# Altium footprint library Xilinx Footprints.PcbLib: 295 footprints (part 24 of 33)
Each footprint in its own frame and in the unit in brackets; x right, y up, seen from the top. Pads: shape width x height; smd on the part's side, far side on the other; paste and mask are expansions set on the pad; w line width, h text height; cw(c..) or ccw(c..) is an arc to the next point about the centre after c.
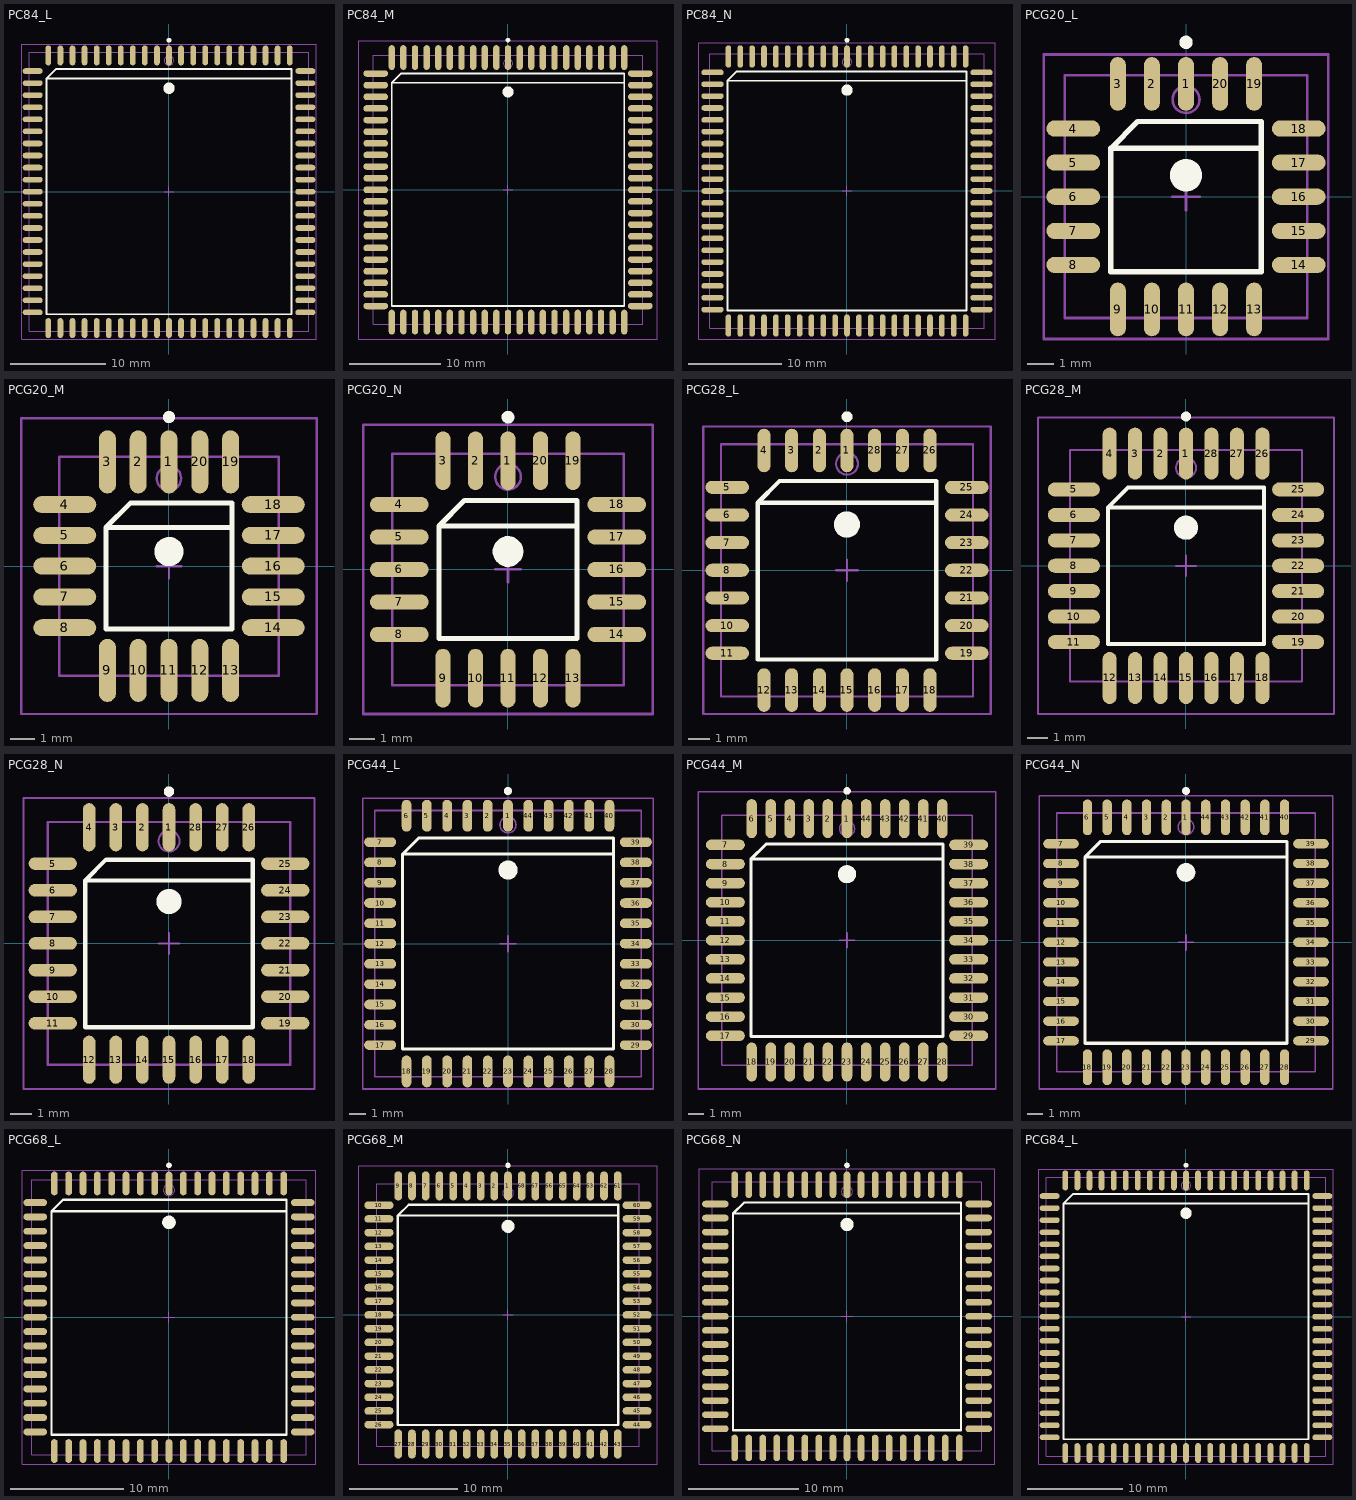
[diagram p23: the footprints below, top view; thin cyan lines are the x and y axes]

## PC84_L [mm] "84-Pin Plastic Leaded Chip Carrier (PC84), IPC High Density"
height 5.08
pads (84):
  oval 0.6x2.1 smd: 1(0,14.35) 2(-1.27,14.35) 3(-2.54,14.35) 4(-3.81,14.35) 5(-5.08,14.35) 6(-6.35,14.35) 7(-7.62,14.35) 8(-8.89,14.35) 9(-10.16,14.35) 10(-11.43,14.35) 11(-12.7,14.35) 33(-12.7,-14.35) 34(-11.43,-14.35) 35(-10.16,-14.35) 36(-8.89,-14.35) 37(-7.62,-14.35) 38(-6.35,-14.35) 39(-5.08,-14.35) 40(-3.81,-14.35) 41(-2.54,-14.35) 42(-1.27,-14.35) 43(0,-14.35) 44(1.27,-14.35) 45(2.54,-14.35) 46(3.81,-14.35) 47(5.08,-14.35) 48(6.35,-14.35) 49(7.62,-14.35) 50(8.89,-14.35) 51(10.16,-14.35) 52(11.43,-14.35) 53(12.7,-14.35) 75(12.7,14.35) 76(11.43,14.35) 77(10.16,14.35) 78(8.89,14.35) 79(7.62,14.35) 80(6.35,14.35) 81(5.08,14.35) 82(3.81,14.35) 83(2.54,14.35) 84(1.27,14.35)
  oval 2.1x0.6 smd: 12(-14.35,12.7) 13(-14.35,11.43) 14(-14.35,10.16) 15(-14.35,8.89) 16(-14.35,7.62) 17(-14.35,6.35) 18(-14.35,5.08) 19(-14.35,3.81) 20(-14.35,2.54) 21(-14.35,1.27) 22(-14.35,0) 23(-14.35,-1.27) 24(-14.35,-2.54) 25(-14.35,-3.81) 26(-14.35,-5.08) 27(-14.35,-6.35) 28(-14.35,-7.62) 29(-14.35,-8.89) 30(-14.35,-10.16) 31(-14.35,-11.43) 32(-14.35,-12.7) 54(14.35,-12.7) 55(14.35,-11.43) 56(14.35,-10.16) 57(14.35,-8.89) 58(14.35,-7.62) 59(14.35,-6.35) 60(14.35,-5.08) 61(14.35,-3.81) 62(14.35,-2.54) 63(14.35,-1.27) 64(14.35,0) 65(14.35,1.27) 66(14.35,2.54) 67(14.35,3.81) 68(14.35,5.08) 69(14.35,6.35) 70(14.35,7.62) 71(14.35,8.89) 72(14.35,10.16) 73(14.35,11.43) 74(14.35,12.7)
Top Overlay:
  circle w0.25: c0,15.95 r0.125
  circle w0.6: c0,10.9 r0.3
  lines w0.2: 12.9,11.9 -12.9,11.9 ; -12.9,11.9 -11.9,12.9 12.9,12.9 12.9,-12.9 -12.9,-12.9 -12.9,11.9
Mechanical 13:
  circle w0.1: c0,13.805 r0.5
  lines w0.1: -14.705,-14.705 -14.705,14.705 14.705,14.705 14.705,-14.705 -14.705,-14.705
Mechanical 15:
  lines w0.1: -0.5,0 0.5,0 ; 0,-0.5 0,0.5 ; -15.5,-15.5 -15.5,15.5 15.5,15.5 15.5,-15.5 -15.5,-15.5
3D body: height 5.08, standoff 0, extent -14.705,-14.705 14.705,14.705

## PC84_M [mm] "84-Pin Plastic Leaded Chip Carrier (PC84), IPC Low Density"
height 5.08
pads (84):
  oval 0.7x2.7 smd: 1(0,14.45) 2(-1.27,14.45) 3(-2.54,14.45) 4(-3.81,14.45) 5(-5.08,14.45) 6(-6.35,14.45) 7(-7.62,14.45) 8(-8.89,14.45) 9(-10.16,14.45) 10(-11.43,14.45) 11(-12.7,14.45) 33(-12.7,-14.45) 34(-11.43,-14.45) 35(-10.16,-14.45) 36(-8.89,-14.45) 37(-7.62,-14.45) 38(-6.35,-14.45) 39(-5.08,-14.45) 40(-3.81,-14.45) 41(-2.54,-14.45) 42(-1.27,-14.45) 43(0,-14.45) 44(1.27,-14.45) 45(2.54,-14.45) 46(3.81,-14.45) 47(5.08,-14.45) 48(6.35,-14.45) 49(7.62,-14.45) 50(8.89,-14.45) 51(10.16,-14.45) 52(11.43,-14.45) 53(12.7,-14.45) 75(12.7,14.45) 76(11.43,14.45) 77(10.16,14.45) 78(8.89,14.45) 79(7.62,14.45) 80(6.35,14.45) 81(5.08,14.45) 82(3.81,14.45) 83(2.54,14.45) 84(1.27,14.45)
  oval 2.7x0.7 smd: 12(-14.45,12.7) 13(-14.45,11.43) 14(-14.45,10.16) 15(-14.45,8.89) 16(-14.45,7.62) 17(-14.45,6.35) 18(-14.45,5.08) 19(-14.45,3.81) 20(-14.45,2.54) 21(-14.45,1.27) 22(-14.45,0) 23(-14.45,-1.27) 24(-14.45,-2.54) 25(-14.45,-3.81) 26(-14.45,-5.08) 27(-14.45,-6.35) 28(-14.45,-7.62) 29(-14.45,-8.89) 30(-14.45,-10.16) 31(-14.45,-11.43) 32(-14.45,-12.7) 54(14.45,-12.7) 55(14.45,-11.43) 56(14.45,-10.16) 57(14.45,-8.89) 58(14.45,-7.62) 59(14.45,-6.35) 60(14.45,-5.08) 61(14.45,-3.81) 62(14.45,-2.54) 63(14.45,-1.27) 64(14.45,0) 65(14.45,1.27) 66(14.45,2.54) 67(14.45,3.81) 68(14.45,5.08) 69(14.45,6.35) 70(14.45,7.62) 71(14.45,8.89) 72(14.45,10.16) 73(14.45,11.43) 74(14.45,12.7)
Top Overlay:
  circle w0.25: c0,16.35 r0.125
  circle w0.6: c0,10.7 r0.3
  lines w0.2: 12.7,11.7 -12.7,11.7 ; -12.7,11.7 -11.7,12.7 12.7,12.7 12.7,-12.7 -12.7,-12.7 -12.7,11.7
Mechanical 13:
  circle w0.1: c0,13.805 r0.5
  lines w0.1: -14.705,-14.705 -14.705,14.705 14.705,14.705 14.705,-14.705 -14.705,-14.705
Mechanical 15:
  lines w0.1: -0.5,0 0.5,0 ; 0,-0.5 0,0.5 ; -16.3,-16.3 -16.3,16.3 16.3,16.3 16.3,-16.3 -16.3,-16.3
3D body: height 5.08, standoff 0, extent -14.705,-14.705 14.705,14.705

## PC84_N [mm] "84-Pin Plastic Leaded Chip Carrier (PC84), IPC Medium Density"
height 5.08
pads (84):
  oval 0.6x2.4 smd: 1(0,14.4) 2(-1.27,14.4) 3(-2.54,14.4) 4(-3.81,14.4) 5(-5.08,14.4) 6(-6.35,14.4) 7(-7.62,14.4) 8(-8.89,14.4) 9(-10.16,14.4) 10(-11.43,14.4) 11(-12.7,14.4) 33(-12.7,-14.4) 34(-11.43,-14.4) 35(-10.16,-14.4) 36(-8.89,-14.4) 37(-7.62,-14.4) 38(-6.35,-14.4) 39(-5.08,-14.4) 40(-3.81,-14.4) 41(-2.54,-14.4) 42(-1.27,-14.4) 43(0,-14.4) 44(1.27,-14.4) 45(2.54,-14.4) 46(3.81,-14.4) 47(5.08,-14.4) 48(6.35,-14.4) 49(7.62,-14.4) 50(8.89,-14.4) 51(10.16,-14.4) 52(11.43,-14.4) 53(12.7,-14.4) 75(12.7,14.4) 76(11.43,14.4) 77(10.16,14.4) 78(8.89,14.4) 79(7.62,14.4) 80(6.35,14.4) 81(5.08,14.4) 82(3.81,14.4) 83(2.54,14.4) 84(1.27,14.4)
  oval 2.4x0.6 smd: 12(-14.4,12.7) 13(-14.4,11.43) 14(-14.4,10.16) 15(-14.4,8.89) 16(-14.4,7.62) 17(-14.4,6.35) 18(-14.4,5.08) 19(-14.4,3.81) 20(-14.4,2.54) 21(-14.4,1.27) 22(-14.4,0) 23(-14.4,-1.27) 24(-14.4,-2.54) 25(-14.4,-3.81) 26(-14.4,-5.08) 27(-14.4,-6.35) 28(-14.4,-7.62) 29(-14.4,-8.89) 30(-14.4,-10.16) 31(-14.4,-11.43) 32(-14.4,-12.7) 54(14.4,-12.7) 55(14.4,-11.43) 56(14.4,-10.16) 57(14.4,-8.89) 58(14.4,-7.62) 59(14.4,-6.35) 60(14.4,-5.08) 61(14.4,-3.81) 62(14.4,-2.54) 63(14.4,-1.27) 64(14.4,0) 65(14.4,1.27) 66(14.4,2.54) 67(14.4,3.81) 68(14.4,5.08) 69(14.4,6.35) 70(14.4,7.62) 71(14.4,8.89) 72(14.4,10.16) 73(14.4,11.43) 74(14.4,12.7)
Top Overlay:
  circle w0.6: c0,10.8 r0.3
  circle w0.25: c0,16.15 r0.125
  lines w0.2: 12.8,11.8 -12.8,11.8 ; -12.8,11.8 -12.8,-12.8 12.8,-12.8 12.8,12.8 -11.8,12.8 -12.8,11.8
Mechanical 13:
  circle w0.1: c0,13.805 r0.5
  lines w0.1: -14.705,-14.705 14.705,-14.705 14.705,14.705 -14.705,14.705 -14.705,-14.705
Mechanical 15:
  lines w0.1: -0.5,0 0.5,0 ; 0,-0.5 0,0.5 ; -15.85,-15.85 15.85,-15.85 15.85,15.85 -15.85,15.85 -15.85,-15.85
3D body: height 5.08, standoff 0, extent -14.705,-14.705 14.705,14.705

## PCG20_L [mm] "20-Pin Plastic Leaded Chip Carrier (PCG20) - Pb-Free, IPC High Density"
height 4.58
pads (20):
  oval 0.6x2 smd: 1(0,4.2) 2(-1.27,4.2) 3(-2.54,4.2) 9(-2.54,-4.2) 10(-1.27,-4.2) 11(0,-4.2) 12(1.27,-4.2) 13(2.54,-4.2) 19(2.54,4.2) 20(1.27,4.2)
  oval 2x0.6 smd: 4(-4.2,2.54) 5(-4.2,1.27) 6(-4.2,0) 7(-4.2,-1.27) 8(-4.2,-2.54) 14(4.2,-2.54) 15(4.2,-1.27) 16(4.2,0) 17(4.2,1.27) 18(4.2,2.54)
Top Overlay:
  circle w0.25: c0,5.75 r0.125
  circle w0.6: c0,0.8 r0.3
  lines w0.2: 2.8,1.8 -2.8,1.8 ; -2.8,1.8 -1.8,2.8 2.8,2.8 2.8,-2.8 -2.8,-2.8 -2.8,1.8
Mechanical 13:
  circle w0.1: c0,3.62 r0.5
  lines w0.1: -4.52,-4.52 -4.52,4.52 4.52,4.52 4.52,-4.52 -4.52,-4.52
Mechanical 15:
  lines w0.1: -0.5,0 0.5,0 ; 0,-0.5 0,0.5 ; -5.3,-5.3 -5.3,5.3 5.3,5.3 5.3,-5.3 -5.3,-5.3
3D body: height 4.58, standoff 0, extent -4.52,-4.52 4.52,4.52

## PCG20_M [mm] "20-Pin Plastic Leaded Chip Carrier (PCG20) - Pb-Free, IPC Low Density"
height 4.58
pads (20):
  oval 0.7x2.6 smd: 1(0,4.3) 2(-1.27,4.3) 3(-2.54,4.3) 9(-2.54,-4.3) 10(-1.27,-4.3) 11(0,-4.3) 12(1.27,-4.3) 13(2.54,-4.3) 19(2.54,4.3) 20(1.27,4.3)
  oval 2.6x0.7 smd: 4(-4.3,2.54) 5(-4.3,1.27) 6(-4.3,0) 7(-4.3,-1.27) 8(-4.3,-2.54) 14(4.3,-2.54) 15(4.3,-1.27) 16(4.3,0) 17(4.3,1.27) 18(4.3,2.54)
Top Overlay:
  circle w0.25: c0,6.15 r0.125
  circle w0.6: c0,0.6 r0.3
  lines w0.2: 2.6,1.6 -2.6,1.6 ; -2.6,1.6 -1.6,2.6 2.6,2.6 2.6,-2.6 -2.6,-2.6 -2.6,1.6
Mechanical 13:
  circle w0.1: c0,3.62 r0.5
  lines w0.1: -4.52,-4.52 -4.52,4.52 4.52,4.52 4.52,-4.52 -4.52,-4.52
Mechanical 15:
  lines w0.1: -0.5,0 0.5,0 ; 0,-0.5 0,0.5 ; -6.1,-6.1 -6.1,6.1 6.1,6.1 6.1,-6.1 -6.1,-6.1
3D body: height 4.58, standoff 0, extent -4.52,-4.52 4.52,4.52

## PCG20_N [mm] "20-Pin Plastic Leaded Chip Carrier (PCG20) - Pb-Free, IPC Medium Density"
height 4.58
pads (20):
  oval 0.6x2.3 smd: 1(0,4.25) 2(-1.27,4.25) 3(-2.54,4.25) 9(-2.54,-4.25) 10(-1.27,-4.25) 11(0,-4.25) 12(1.27,-4.25) 13(2.54,-4.25) 19(2.54,4.25) 20(1.27,4.25)
  oval 2.3x0.6 smd: 4(-4.25,2.54) 5(-4.25,1.27) 6(-4.25,0) 7(-4.25,-1.27) 8(-4.25,-2.54) 14(4.25,-2.54) 15(4.25,-1.27) 16(4.25,0) 17(4.25,1.27) 18(4.25,2.54)
Top Overlay:
  circle w0.6: c0,0.7 r0.3
  circle w0.25: c0,5.95 r0.125
  lines w0.2: 2.7,1.7 -2.7,1.7 ; -2.7,1.7 -2.7,-2.7 2.7,-2.7 2.7,2.7 -1.7,2.7 -2.7,1.7
Mechanical 13:
  circle w0.1: c0,3.62 r0.5
  lines w0.1: -4.52,-4.52 4.52,-4.52 4.52,4.52 -4.52,4.52 -4.52,-4.52
Mechanical 15:
  lines w0.1: -0.5,0 0.5,0 ; 0,-0.5 0,0.5 ; -5.65,-5.65 5.65,-5.65 5.65,5.65 -5.65,5.65 -5.65,-5.65
3D body: height 4.58, standoff 0, extent -4.52,-4.52 4.52,4.52

## PCG28_L [mm] "28-Pin Plastic Leaded Chip Carrier (PCG28) - Pb-Free, IPC High Density"
height 4.58
pads (28):
  oval 0.6x2 smd: 1(0,5.5) 2(-1.27,5.5) 3(-2.54,5.5) 4(-3.81,5.5) 12(-3.81,-5.5) 13(-2.54,-5.5) 14(-1.27,-5.5) 15(0,-5.5) 16(1.27,-5.5) 17(2.54,-5.5) 18(3.81,-5.5) 26(3.81,5.5) 27(2.54,5.5) 28(1.27,5.5)
  oval 2x0.6 smd: 5(-5.5,3.81) 6(-5.5,2.54) 7(-5.5,1.27) 8(-5.5,0) 9(-5.5,-1.27) 10(-5.5,-2.54) 11(-5.5,-3.81) 19(5.5,-3.81) 20(5.5,-2.54) 21(5.5,-1.27) 22(5.5,0) 23(5.5,1.27) 24(5.5,2.54) 25(5.5,3.81)
Top Overlay:
  circle w0.25: c0,7.05 r0.125
  circle w0.6: c0,2.1 r0.3
  lines w0.2: 4.1,3.1 -4.1,3.1 ; -4.1,3.1 -3.1,4.1 4.1,4.1 4.1,-4.1 -4.1,-4.1 -4.1,3.1
Mechanical 13:
  circle w0.1: c0,4.89 r0.5
  lines w0.1: -5.79,-5.79 -5.79,5.79 5.79,5.79 5.79,-5.79 -5.79,-5.79
Mechanical 15:
  lines w0.1: -0.5,0 0.5,0 ; 0,-0.5 0,0.5 ; -6.6,-6.6 -6.6,6.6 6.6,6.6 6.6,-6.6 -6.6,-6.6
3D body: height 4.58, standoff 0, extent -5.79,-5.79 5.79,5.79

## PCG28_M [mm] "28-Pin Plastic Leaded Chip Carrier (PCG28) - Pb-Free, IPC Low Density"
height 4.58
pads (28):
  oval 0.7x2.6 smd: 1(0,5.6) 2(-1.27,5.6) 3(-2.54,5.6) 4(-3.81,5.6) 12(-3.81,-5.6) 13(-2.54,-5.6) 14(-1.27,-5.6) 15(0,-5.6) 16(1.27,-5.6) 17(2.54,-5.6) 18(3.81,-5.6) 26(3.81,5.6) 27(2.54,5.6) 28(1.27,5.6)
  oval 2.6x0.7 smd: 5(-5.6,3.81) 6(-5.6,2.54) 7(-5.6,1.27) 8(-5.6,0) 9(-5.6,-1.27) 10(-5.6,-2.54) 11(-5.6,-3.81) 19(5.6,-3.81) 20(5.6,-2.54) 21(5.6,-1.27) 22(5.6,0) 23(5.6,1.27) 24(5.6,2.54) 25(5.6,3.81)
Top Overlay:
  circle w0.25: c0,7.45 r0.125
  circle w0.6: c0,1.9 r0.3
  lines w0.2: 3.9,2.9 -3.9,2.9 ; -3.9,2.9 -2.9,3.9 3.9,3.9 3.9,-3.9 -3.9,-3.9 -3.9,2.9
Mechanical 13:
  circle w0.1: c0,4.89 r0.5
  lines w0.1: -5.79,-5.79 -5.79,5.79 5.79,5.79 5.79,-5.79 -5.79,-5.79
Mechanical 15:
  lines w0.1: -0.5,0 0.5,0 ; 0,-0.5 0,0.5 ; -7.4,-7.4 -7.4,7.4 7.4,7.4 7.4,-7.4 -7.4,-7.4
3D body: height 4.58, standoff 0, extent -5.79,-5.79 5.79,5.79

## PCG28_N [mm] "28-Pin Plastic Leaded Chip Carrier (PCG28) - Pb-Free, IPC Medium Density"
height 4.58
pads (28):
  oval 0.6x2.3 smd: 1(0,5.55) 2(-1.27,5.55) 3(-2.54,5.55) 4(-3.81,5.55) 12(-3.81,-5.55) 13(-2.54,-5.55) 14(-1.27,-5.55) 15(0,-5.55) 16(1.27,-5.55) 17(2.54,-5.55) 18(3.81,-5.55) 26(3.81,5.55) 27(2.54,5.55) 28(1.27,5.55)
  oval 2.3x0.6 smd: 5(-5.55,3.81) 6(-5.55,2.54) 7(-5.55,1.27) 8(-5.55,0) 9(-5.55,-1.27) 10(-5.55,-2.54) 11(-5.55,-3.81) 19(5.55,-3.81) 20(5.55,-2.54) 21(5.55,-1.27) 22(5.55,0) 23(5.55,1.27) 24(5.55,2.54) 25(5.55,3.81)
Top Overlay:
  circle w0.25: c0,7.25 r0.125
  circle w0.6: c0,2 r0.3
  lines w0.2: 4,3 -4,3 ; -4,3 -3,4 4,4 4,-4 -4,-4 -4,3
Mechanical 13:
  circle w0.1: c0,4.89 r0.5
  lines w0.1: -5.79,-5.79 -5.79,5.79 5.79,5.79 5.79,-5.79 -5.79,-5.79
Mechanical 15:
  lines w0.1: -0.5,0 0.5,0 ; 0,-0.5 0,0.5 ; -6.95,-6.95 -6.95,6.95 6.95,6.95 6.95,-6.95 -6.95,-6.95
3D body: height 4.58, standoff 0, extent -5.79,-5.79 5.79,5.79

## PCG44_L [mm] "44-Pin Plastic Leaded Chip Carrier (PCG44) - Pb-Free, IPC High Density"
height 4.58
pads (44):
  oval 0.6x2 smd: 1(0,8) 2(-1.27,8) 3(-2.54,8) 4(-3.81,8) 5(-5.08,8) 6(-6.35,8) 18(-6.35,-8) 19(-5.08,-8) 20(-3.81,-8) 21(-2.54,-8) 22(-1.27,-8) 23(0,-8) 24(1.27,-8) 25(2.54,-8) 26(3.81,-8) 27(5.08,-8) 28(6.35,-8) 40(6.35,8) 41(5.08,8) 42(3.81,8) 43(2.54,8) 44(1.27,8)
  oval 2x0.6 smd: 7(-8,6.35) 8(-8,5.08) 9(-8,3.81) 10(-8,2.54) 11(-8,1.27) 12(-8,0) 13(-8,-1.27) 14(-8,-2.54) 15(-8,-3.81) 16(-8,-5.08) 17(-8,-6.35) 29(8,-6.35) 30(8,-5.08) 31(8,-3.81) 32(8,-2.54) 33(8,-1.27) 34(8,0) 35(8,1.27) 36(8,2.54) 37(8,3.81) 38(8,5.08) 39(8,6.35)
Top Overlay:
  circle w0.25: c0,9.55 r0.125
  circle w0.6: c0,4.6 r0.3
  lines w0.2: 6.6,5.6 -6.6,5.6 ; -6.6,5.6 -5.6,6.6 6.6,6.6 6.6,-6.6 -6.6,-6.6 -6.6,5.6
Mechanical 13:
  circle w0.1: c0,7.43 r0.5
  lines w0.1: -8.33,-8.33 -8.33,8.33 8.33,8.33 8.33,-8.33 -8.33,-8.33
Mechanical 15:
  lines w0.1: -0.5,0 0.5,0 ; 0,-0.5 0,0.5 ; -9.1,-9.1 -9.1,9.1 9.1,9.1 9.1,-9.1 -9.1,-9.1
3D body: height 4.58, standoff 0, extent -8.33,-8.33 8.33,8.33

## PCG44_M [mm] "44-Pin Plastic Leaded Chip Carrier (PCG44) - Pb-Free, IPC Low Density"
height 4.58
pads (44):
  oval 0.7x2.6 smd: 1(0,8.1) 2(-1.27,8.1) 3(-2.54,8.1) 4(-3.81,8.1) 5(-5.08,8.1) 6(-6.35,8.1) 18(-6.35,-8.1) 19(-5.08,-8.1) 20(-3.81,-8.1) 21(-2.54,-8.1) 22(-1.27,-8.1) 23(0,-8.1) 24(1.27,-8.1) 25(2.54,-8.1) 26(3.81,-8.1) 27(5.08,-8.1) 28(6.35,-8.1) 40(6.35,8.1) 41(5.08,8.1) 42(3.81,8.1) 43(2.54,8.1) 44(1.27,8.1)
  oval 2.6x0.7 smd: 7(-8.1,6.35) 8(-8.1,5.08) 9(-8.1,3.81) 10(-8.1,2.54) 11(-8.1,1.27) 12(-8.1,0) 13(-8.1,-1.27) 14(-8.1,-2.54) 15(-8.1,-3.81) 16(-8.1,-5.08) 17(-8.1,-6.35) 29(8.1,-6.35) 30(8.1,-5.08) 31(8.1,-3.81) 32(8.1,-2.54) 33(8.1,-1.27) 34(8.1,0) 35(8.1,1.27) 36(8.1,2.54) 37(8.1,3.81) 38(8.1,5.08) 39(8.1,6.35)
Top Overlay:
  circle w0.25: c0,9.95 r0.125
  circle w0.6: c0,4.4 r0.3
  lines w0.2: 6.4,5.4 -6.4,5.4 ; -6.4,5.4 -5.4,6.4 6.4,6.4 6.4,-6.4 -6.4,-6.4 -6.4,5.4
Mechanical 13:
  circle w0.1: c0,7.43 r0.5
  lines w0.1: -8.33,-8.33 -8.33,8.33 8.33,8.33 8.33,-8.33 -8.33,-8.33
Mechanical 15:
  lines w0.1: -0.5,0 0.5,0 ; 0,-0.5 0,0.5 ; -9.9,-9.9 -9.9,9.9 9.9,9.9 9.9,-9.9 -9.9,-9.9
3D body: height 4.58, standoff 0, extent -8.33,-8.33 8.33,8.33

## PCG44_N [mm] "44-Pin Plastic Leaded Chip Carrier (PCG44) - Pb-Free, IPC Medium Density"
height 4.58
pads (44):
  oval 0.6x2.3 smd: 1(0,8.05) 2(-1.27,8.05) 3(-2.54,8.05) 4(-3.81,8.05) 5(-5.08,8.05) 6(-6.35,8.05) 18(-6.35,-8.05) 19(-5.08,-8.05) 20(-3.81,-8.05) 21(-2.54,-8.05) 22(-1.27,-8.05) 23(0,-8.05) 24(1.27,-8.05) 25(2.54,-8.05) 26(3.81,-8.05) 27(5.08,-8.05) 28(6.35,-8.05) 40(6.35,8.05) 41(5.08,8.05) 42(3.81,8.05) 43(2.54,8.05) 44(1.27,8.05)
  oval 2.3x0.6 smd: 7(-8.05,6.35) 8(-8.05,5.08) 9(-8.05,3.81) 10(-8.05,2.54) 11(-8.05,1.27) 12(-8.05,0) 13(-8.05,-1.27) 14(-8.05,-2.54) 15(-8.05,-3.81) 16(-8.05,-5.08) 17(-8.05,-6.35) 29(8.05,-6.35) 30(8.05,-5.08) 31(8.05,-3.81) 32(8.05,-2.54) 33(8.05,-1.27) 34(8.05,0) 35(8.05,1.27) 36(8.05,2.54) 37(8.05,3.81) 38(8.05,5.08) 39(8.05,6.35)
Top Overlay:
  circle w0.6: c0,4.5 r0.3
  circle w0.25: c0,9.75 r0.125
  lines w0.2: 6.5,5.5 -6.5,5.5 ; -6.5,5.5 -6.5,-6.5 6.5,-6.5 6.5,6.5 -5.5,6.5 -6.5,5.5
Mechanical 13:
  circle w0.1: c0,7.43 r0.5
  lines w0.1: -8.33,-8.33 8.33,-8.33 8.33,8.33 -8.33,8.33 -8.33,-8.33
Mechanical 15:
  lines w0.1: -0.5,0 0.5,0 ; 0,-0.5 0,0.5 ; -9.45,-9.45 9.45,-9.45 9.45,9.45 -9.45,9.45 -9.45,-9.45
3D body: height 4.58, standoff 0, extent -8.33,-8.33 8.33,8.33

## PCG68_L [mm] "68-Pin Plastic Leaded Chip Carrier (PCG68) - Pb-Free, IPC High Density"
height 5.08
pads (68):
  oval 0.6x2.1 smd: 1(0,11.85) 2(-1.27,11.85) 3(-2.54,11.85) 4(-3.81,11.85) 5(-5.08,11.85) 6(-6.35,11.85) 7(-7.62,11.85) 8(-8.89,11.85) 9(-10.16,11.85) 27(-10.16,-11.85) 28(-8.89,-11.85) 29(-7.62,-11.85) 30(-6.35,-11.85) 31(-5.08,-11.85) 32(-3.81,-11.85) 33(-2.54,-11.85) 34(-1.27,-11.85) 35(0,-11.85) 36(1.27,-11.85) 37(2.54,-11.85) 38(3.81,-11.85) 39(5.08,-11.85) 40(6.35,-11.85) 41(7.62,-11.85) 42(8.89,-11.85) 43(10.16,-11.85) 61(10.16,11.85) 62(8.89,11.85) 63(7.62,11.85) 64(6.35,11.85) 65(5.08,11.85) 66(3.81,11.85) 67(2.54,11.85) 68(1.27,11.85)
  oval 2.1x0.6 smd: 10(-11.85,10.16) 11(-11.85,8.89) 12(-11.85,7.62) 13(-11.85,6.35) 14(-11.85,5.08) 15(-11.85,3.81) 16(-11.85,2.54) 17(-11.85,1.27) 18(-11.85,0) 19(-11.85,-1.27) 20(-11.85,-2.54) 21(-11.85,-3.81) 22(-11.85,-5.08) 23(-11.85,-6.35) 24(-11.85,-7.62) 25(-11.85,-8.89) 26(-11.85,-10.16) 44(11.85,-10.16) 45(11.85,-8.89) 46(11.85,-7.62) 47(11.85,-6.35) 48(11.85,-5.08) 49(11.85,-3.81) 50(11.85,-2.54) 51(11.85,-1.27) 52(11.85,0) 53(11.85,1.27) 54(11.85,2.54) 55(11.85,3.81) 56(11.85,5.08) 57(11.85,6.35) 58(11.85,7.62) 59(11.85,8.89) 60(11.85,10.16)
Top Overlay:
  circle w0.25: c0,13.45 r0.125
  circle w0.6: c0,8.4 r0.3
  lines w0.2: 10.4,9.4 -10.4,9.4 ; -10.4,9.4 -9.4,10.4 10.4,10.4 10.4,-10.4 -10.4,-10.4 -10.4,9.4
Mechanical 13:
  circle w0.1: c0,11.265 r0.5
  lines w0.1: -12.165,-12.165 -12.165,12.165 12.165,12.165 12.165,-12.165 -12.165,-12.165
Mechanical 15:
  lines w0.1: -0.5,0 0.5,0 ; 0,-0.5 0,0.5 ; -13,-13 -13,13 13,13 13,-13 -13,-13
3D body: height 5.08, standoff 0, extent -12.165,-12.165 12.165,12.165

## PCG68_M [mm] "68-Pin Plastic Leaded Chip Carrier (PCG68) - Pb-Free, IPC Low Density"
height 5.08
pads (68):
  oval 0.7x2.7 smd: 1(0,11.95) 2(-1.27,11.95) 3(-2.54,11.95) 4(-3.81,11.95) 5(-5.08,11.95) 6(-6.35,11.95) 7(-7.62,11.95) 8(-8.89,11.95) 9(-10.16,11.95) 27(-10.16,-11.95) 28(-8.89,-11.95) 29(-7.62,-11.95) 30(-6.35,-11.95) 31(-5.08,-11.95) 32(-3.81,-11.95) 33(-2.54,-11.95) 34(-1.27,-11.95) 35(0,-11.95) 36(1.27,-11.95) 37(2.54,-11.95) 38(3.81,-11.95) 39(5.08,-11.95) 40(6.35,-11.95) 41(7.62,-11.95) 42(8.89,-11.95) 43(10.16,-11.95) 61(10.16,11.95) 62(8.89,11.95) 63(7.62,11.95) 64(6.35,11.95) 65(5.08,11.95) 66(3.81,11.95) 67(2.54,11.95) 68(1.27,11.95)
  oval 2.7x0.7 smd: 10(-11.95,10.16) 11(-11.95,8.89) 12(-11.95,7.62) 13(-11.95,6.35) 14(-11.95,5.08) 15(-11.95,3.81) 16(-11.95,2.54) 17(-11.95,1.27) 18(-11.95,0) 19(-11.95,-1.27) 20(-11.95,-2.54) 21(-11.95,-3.81) 22(-11.95,-5.08) 23(-11.95,-6.35) 24(-11.95,-7.62) 25(-11.95,-8.89) 26(-11.95,-10.16) 44(11.95,-10.16) 45(11.95,-8.89) 46(11.95,-7.62) 47(11.95,-6.35) 48(11.95,-5.08) 49(11.95,-3.81) 50(11.95,-2.54) 51(11.95,-1.27) 52(11.95,0) 53(11.95,1.27) 54(11.95,2.54) 55(11.95,3.81) 56(11.95,5.08) 57(11.95,6.35) 58(11.95,7.62) 59(11.95,8.89) 60(11.95,10.16)
Top Overlay:
  circle w0.25: c0,13.85 r0.125
  circle w0.6: c0,8.2 r0.3
  lines w0.2: 10.2,9.2 -10.2,9.2 ; -10.2,9.2 -9.2,10.2 10.2,10.2 10.2,-10.2 -10.2,-10.2 -10.2,9.2
Mechanical 13:
  circle w0.1: c0,11.265 r0.5
  lines w0.1: -12.165,-12.165 -12.165,12.165 12.165,12.165 12.165,-12.165 -12.165,-12.165
Mechanical 15:
  lines w0.1: -0.5,0 0.5,0 ; 0,-0.5 0,0.5 ; -13.8,-13.8 -13.8,13.8 13.8,13.8 13.8,-13.8 -13.8,-13.8
3D body: height 5.08, standoff 0, extent -12.165,-12.165 12.165,12.165

## PCG68_N [mm] "68-Pin Plastic Leaded Chip Carrier (PCG68) - Pb-Free, IPC Medium Density"
height 5.08
pads (68):
  oval 0.6x2.4 smd: 1(0,11.9) 2(-1.27,11.9) 3(-2.54,11.9) 4(-3.81,11.9) 5(-5.08,11.9) 6(-6.35,11.9) 7(-7.62,11.9) 8(-8.89,11.9) 9(-10.16,11.9) 27(-10.16,-11.9) 28(-8.89,-11.9) 29(-7.62,-11.9) 30(-6.35,-11.9) 31(-5.08,-11.9) 32(-3.81,-11.9) 33(-2.54,-11.9) 34(-1.27,-11.9) 35(0,-11.9) 36(1.27,-11.9) 37(2.54,-11.9) 38(3.81,-11.9) 39(5.08,-11.9) 40(6.35,-11.9) 41(7.62,-11.9) 42(8.89,-11.9) 43(10.16,-11.9) 61(10.16,11.9) 62(8.89,11.9) 63(7.62,11.9) 64(6.35,11.9) 65(5.08,11.9) 66(3.81,11.9) 67(2.54,11.9) 68(1.27,11.9)
  oval 2.4x0.6 smd: 10(-11.9,10.16) 11(-11.9,8.89) 12(-11.9,7.62) 13(-11.9,6.35) 14(-11.9,5.08) 15(-11.9,3.81) 16(-11.9,2.54) 17(-11.9,1.27) 18(-11.9,0) 19(-11.9,-1.27) 20(-11.9,-2.54) 21(-11.9,-3.81) 22(-11.9,-5.08) 23(-11.9,-6.35) 24(-11.9,-7.62) 25(-11.9,-8.89) 26(-11.9,-10.16) 44(11.9,-10.16) 45(11.9,-8.89) 46(11.9,-7.62) 47(11.9,-6.35) 48(11.9,-5.08) 49(11.9,-3.81) 50(11.9,-2.54) 51(11.9,-1.27) 52(11.9,0) 53(11.9,1.27) 54(11.9,2.54) 55(11.9,3.81) 56(11.9,5.08) 57(11.9,6.35) 58(11.9,7.62) 59(11.9,8.89) 60(11.9,10.16)
Top Overlay:
  circle w0.25: c0,13.65 r0.125
  circle w0.6: c0,8.3 r0.3
  lines w0.2: 10.3,9.3 -10.3,9.3 ; -10.3,9.3 -9.3,10.3 10.3,10.3 10.3,-10.3 -10.3,-10.3 -10.3,9.3
Mechanical 13:
  circle w0.1: c0,11.265 r0.5
  lines w0.1: -12.165,-12.165 -12.165,12.165 12.165,12.165 12.165,-12.165 -12.165,-12.165
Mechanical 15:
  lines w0.1: -0.5,0 0.5,0 ; 0,-0.5 0,0.5 ; -13.35,-13.35 -13.35,13.35 13.35,13.35 13.35,-13.35 -13.35,-13.35
3D body: height 5.08, standoff 0, extent -12.165,-12.165 12.165,12.165

## PCG84_L [mm] "84-Pin Plastic Leaded Chip Carrier (PCG84) - Pb-Free, IPC High Density"
height 5.08
pads (84):
  oval 0.6x2.1 smd: 1(0,14.35) 2(-1.27,14.35) 3(-2.54,14.35) 4(-3.81,14.35) 5(-5.08,14.35) 6(-6.35,14.35) 7(-7.62,14.35) 8(-8.89,14.35) 9(-10.16,14.35) 10(-11.43,14.35) 11(-12.7,14.35) 33(-12.7,-14.35) 34(-11.43,-14.35) 35(-10.16,-14.35) 36(-8.89,-14.35) 37(-7.62,-14.35) 38(-6.35,-14.35) 39(-5.08,-14.35) 40(-3.81,-14.35) 41(-2.54,-14.35) 42(-1.27,-14.35) 43(0,-14.35) 44(1.27,-14.35) 45(2.54,-14.35) 46(3.81,-14.35) 47(5.08,-14.35) 48(6.35,-14.35) 49(7.62,-14.35) 50(8.89,-14.35) 51(10.16,-14.35) 52(11.43,-14.35) 53(12.7,-14.35) 75(12.7,14.35) 76(11.43,14.35) 77(10.16,14.35) 78(8.89,14.35) 79(7.62,14.35) 80(6.35,14.35) 81(5.08,14.35) 82(3.81,14.35) 83(2.54,14.35) 84(1.27,14.35)
  oval 2.1x0.6 smd: 12(-14.35,12.7) 13(-14.35,11.43) 14(-14.35,10.16) 15(-14.35,8.89) 16(-14.35,7.62) 17(-14.35,6.35) 18(-14.35,5.08) 19(-14.35,3.81) 20(-14.35,2.54) 21(-14.35,1.27) 22(-14.35,0) 23(-14.35,-1.27) 24(-14.35,-2.54) 25(-14.35,-3.81) 26(-14.35,-5.08) 27(-14.35,-6.35) 28(-14.35,-7.62) 29(-14.35,-8.89) 30(-14.35,-10.16) 31(-14.35,-11.43) 32(-14.35,-12.7) 54(14.35,-12.7) 55(14.35,-11.43) 56(14.35,-10.16) 57(14.35,-8.89) 58(14.35,-7.62) 59(14.35,-6.35) 60(14.35,-5.08) 61(14.35,-3.81) 62(14.35,-2.54) 63(14.35,-1.27) 64(14.35,0) 65(14.35,1.27) 66(14.35,2.54) 67(14.35,3.81) 68(14.35,5.08) 69(14.35,6.35) 70(14.35,7.62) 71(14.35,8.89) 72(14.35,10.16) 73(14.35,11.43) 74(14.35,12.7)
Top Overlay:
  circle w0.25: c0,15.95 r0.125
  circle w0.6: c0,10.9 r0.3
  lines w0.2: 12.9,11.9 -12.9,11.9 ; -12.9,11.9 -11.9,12.9 12.9,12.9 12.9,-12.9 -12.9,-12.9 -12.9,11.9
Mechanical 13:
  circle w0.1: c0,13.805 r0.5
  lines w0.1: -14.705,-14.705 -14.705,14.705 14.705,14.705 14.705,-14.705 -14.705,-14.705
Mechanical 15:
  lines w0.1: -0.5,0 0.5,0 ; 0,-0.5 0,0.5 ; -15.5,-15.5 -15.5,15.5 15.5,15.5 15.5,-15.5 -15.5,-15.5
3D body: height 5.08, standoff 0, extent -14.705,-14.705 14.705,14.705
